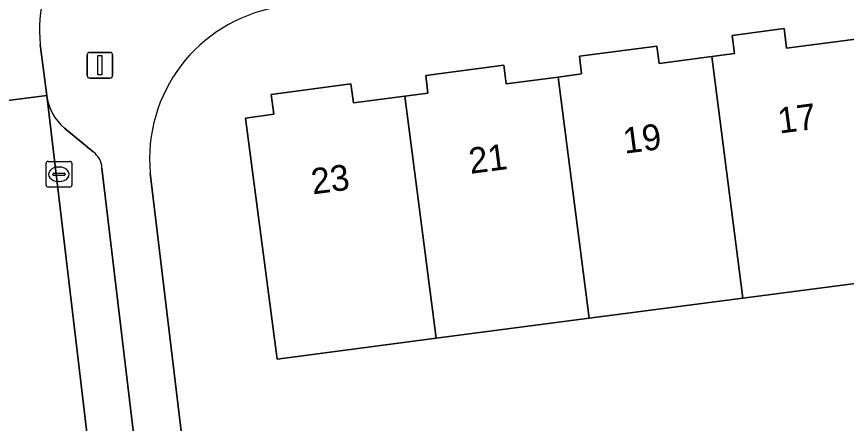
# Model space of a CAD drawing. Extents: x 162073 to 163043, y 381818 to 382561.
# Drawn here: x 162346.87 to 162379.08, y 382430.04 to 382445.83 of the extents above; entities that cross this region are included whole.
import ezdxf

# ---------------------------------------------------------------- set-up
doc = ezdxf.new("R2010")
doc.units = 0
for name, color, linetype in [('IMGEO_Erf', 7, 'Continuous'), ('IMGEO_Kolk', 7, 'Continuous'), ('IMGEO_Lichtmast', 7, 'Continuous'), ('IMGEO_Pand', 7, 'Continuous'), ('IMGEO_Pand_nummerreeks', 7, 'Continuous'), ('IMGEO_Parkeervlak_open', 7, 'Continuous'), ('IMGEO_Rijbaan_lokaal_open', 7, 'Continuous'), ('IMGEO_Voetpad_open', 7, 'Continuous')]:
    doc.layers.add(name, color=color, linetype=linetype)

msp = doc.modelspace()

# ---------------------------------------------------------------- linework, layer by layer
at = {"layer": 'IMGEO_Erf'}
for points in [[(162381.014, 382435.677), (162375.057, 382434.898), (162369.099, 382434.119), (162363.15, 382433.341), (162356.984, 382432.535), (162355.76, 382441.893), (162356.859, 382442.037), (162356.757, 382442.811), (162359.846, 382443.215), (162359.943, 382442.478), (162361.935, 382442.739), (162362.839, 382442.857), (162362.749, 382443.547), (162365.783, 382443.943), (162365.878, 382443.221), (162367.889, 382443.484), (162368.803, 382443.603), (162368.714, 382444.288), (162371.726, 382444.682), (162371.814, 382444.01), (162373.862, 382444.278), (162374.734, 382444.392), (162374.642, 382445.1), (162376.661, 382445.364), (162376.76, 382444.604), (162379.833, 382445.006)], [(162352.061, 382439.747), (162354.358, 382420.586), (162360.628, 382421.338), (162360.286, 382423.951), (162364.504, 382424.503), (162364.846, 382421.889), (162366.651, 382422.117), (162366.319, 382424.655), (162370.255, 382425.17), (162370.594, 382422.547), (162372.552, 382422.803), (162372.209, 382425.425), (162376.197, 382425.947), (162376.532, 382423.323), (162378.405, 382423.569), (162378.063, 382426.191), (162382.258, 382426.74), (162382.601, 382424.117), (162407.339, 382427.254), (162407.316, 382427.433), (162405.814, 382438.92)]]:
    msp.add_lwpolyline(points, dxfattribs=at)
msp.add_arc((162357.987, 382440.319), 5.954, 99.9538, 185.5129, dxfattribs=at)
at = {"layer": 'IMGEO_Kolk'}
for p, q in [((162348.015, 382439.284), (162348.015, 382440.136)), ((162348.09, 382440.21), (162348.942, 382440.21)), ((162348.503, 382439.99), (162348.528, 382439.99)), ((162349.016, 382440.136), (162349.016, 382439.284)), ((162348.274, 382439.704), (162348.274, 382439.716)), ((162348.712, 382439.667), (162348.314, 382439.667)), ((162348.317, 382439.753), (162348.715, 382439.753)), ((162348.758, 382439.716), (162348.758, 382439.704)), ((162348.526, 382439.43), (162348.501, 382439.43)), ((162348.942, 382439.21), (162348.09, 382439.21))]:
    msp.add_line(p, q, dxfattribs=at)
for points in [[(162348.015, 382439.284), (162348.015, 382440.136)], [(162348.09, 382440.21), (162348.942, 382440.21)], [(162349.016, 382440.136), (162349.016, 382439.284)], [(162348.942, 382439.21), (162348.09, 382439.21)]]:
    msp.add_lwpolyline(points, dxfattribs=at)
for centre, radius, start, end in [((162348.092, 382440.134), 0.0765, 91.552, 178.448), ((162348.092, 382440.134), 0.0765, 91.552, 178.448), ((162348.94, 382440.134), 0.0765, 1.552, 88.448), ((162348.94, 382440.134), 0.0765, 1.552, 88.448), ((162348.314, 382439.713), 0.0403, 85.8775, 175.7526), ((162348.311, 382439.703), 0.0366, 178.938, 274.7102), ((162348.715, 382439.71), 0.043, 264.8664, 352.4533), ((162348.719, 382439.715), 0.0386, 1.7309, 96.639), ((162348.092, 382439.286), 0.0765, 181.552, 268.448), ((162348.092, 382439.286), 0.0765, 181.552, 268.448), ((162348.94, 382439.286), 0.0765, 271.552, 358.448), ((162348.94, 382439.286), 0.0765, 271.552, 358.448)]:
    msp.add_arc(centre, radius, start, end, dxfattribs=at)
for centre, major_axis, ratio, start_param, end_param in [((162348.502, 382439.71), (-0.387, 0.002), 0.722429, 4.712389, 7.853982), ((162348.527, 382439.71), (-0.39, 0.002), 0.717154, 1.570796, 4.712389)]:
    msp.add_ellipse(centre, major_axis=major_axis, ratio=ratio, start_param=start_param, end_param=end_param, dxfattribs=at)
at = {"layer": 'IMGEO_Lichtmast'}
for p, q in [((162349.609, 382443.54), (162349.609, 382444.34)), ((162349.609, 382444.34), (162349.609, 382443.54)), ((162349.709, 382444.44), (162350.499, 382444.44)), ((162350.499, 382444.44), (162349.709, 382444.44)), ((162350.599, 382444.34), (162350.599, 382443.54)), ((162350.599, 382443.54), (162350.599, 382444.34)), ((162350.499, 382443.44), (162349.709, 382443.44)), ((162349.709, 382443.44), (162350.499, 382443.44))]:
    msp.add_line(p, q, dxfattribs=at)
msp.add_lwpolyline([(162350.029, 382444.315), (162350.179, 382444.315), (162350.179, 382443.565), (162350.029, 382443.565), (162350.029, 382444.315)], dxfattribs=at)
for centre, start, end in [((162349.709, 382444.34), 90, 180), ((162349.709, 382444.34), 90, 180), ((162350.499, 382444.34), 0, 90), ((162350.499, 382444.34), 360, 90), ((162349.709, 382443.54), 180, 270), ((162349.709, 382443.54), 180, 270), ((162350.499, 382443.54), 270, 0), ((162350.499, 382443.54), 270, 0)]:
    msp.add_arc(centre, 0.1, start, end, dxfattribs=at)
at = {"layer": 'IMGEO_Pand'}
for points in [[(162381.014, 382435.677), (162379.833, 382445.006), (162376.76, 382444.604), (162376.661, 382445.364), (162374.642, 382445.1), (162374.734, 382444.392), (162373.862, 382444.278), (162375.057, 382434.898)], [(162375.057, 382434.898), (162373.862, 382444.278), (162371.814, 382444.01), (162371.726, 382444.682), (162368.714, 382444.288), (162368.803, 382443.603), (162367.889, 382443.484), (162369.099, 382434.119)], [(162363.15, 382433.341), (162369.099, 382434.119), (162367.889, 382443.484), (162365.878, 382443.221), (162365.783, 382443.943), (162362.749, 382443.547), (162362.839, 382442.857), (162361.935, 382442.739)], [(162363.15, 382433.341), (162361.935, 382442.739), (162359.943, 382442.478), (162359.846, 382443.215), (162356.757, 382442.811), (162356.859, 382442.037), (162355.76, 382441.893), (162356.984, 382432.535)]]:
    msp.add_lwpolyline(points, close=True, dxfattribs=at)
at = {"layer": 'IMGEO_Parkeervlak_open'}
for points in [[(162348.044, 382442.765), (162351.073, 382417.25), (162359.505, 382347.328), (162359.881, 382344.208), (162361.255, 382332.813), (162367.454, 382281.495)], [(162349.842, 382440.581), (162348.727, 382441.502)], [(162353.149, 382407.065), (162354.1, 382407.187), (162352.789, 382418.064), (162350.184, 382439.951)]]:
    msp.add_lwpolyline(points, dxfattribs=at)
for centre, radius, start, end in [((162349.995, 382443.004), 1.966, 186.9815, 229.8254), ((162349.331, 382439.896), 0.855, 3.7124, 53.2789)]:
    msp.add_arc(centre, radius, start, end, dxfattribs=at)
at = {"layer": 'IMGEO_Rijbaan_lokaal_open'}
msp.add_lwpolyline([(162342.805, 382444.312), (162342.93, 382443.354), (162343.079, 382442.137), (162348.044, 382442.765), (162347.791, 382444.746)], dxfattribs=at)
msp.add_lwpolyline([(162351.073, 382417.25), (162348.044, 382442.765), (162343.079, 382442.137), (162343.442, 382439.175), (162343.465, 382438.988), (162344.493, 382430.544), (162344.514, 382430.375), (162344.521, 382430.302), (162344.575, 382429.775), (162345.223, 382424.582), (162345.763, 382419.899), (162354.563, 382346.738), (162359.505, 382347.328)], close=True, dxfattribs=at)
msp.add_arc((162352.649, 382445.321), 4.892, 94.6048, 186.7523, dxfattribs=at)
at = {"layer": 'IMGEO_Voetpad_open'}
for points in [[(162347.791, 382444.746), (162348.044, 382442.765)], [(162348.727, 382441.502), (162349.842, 382440.581)], [(162350.184, 382439.951), (162352.789, 382418.064), (162354.1, 382407.187), (162353.149, 382407.065)], [(162368.764, 382300.425), (162368.571, 382302.036), (162363.534, 382344.049), (162363.351, 382345.572), (162359.035, 382381.573), (162358.854, 382383.086), (162354.525, 382419.192), (162354.358, 382420.586), (162352.061, 382439.747)]]:
    msp.add_lwpolyline(points, dxfattribs=at)
for centre, radius, start, end in [((162352.649, 382445.321), 4.892, 94.6048, 186.7523), ((162357.987, 382440.319), 5.954, 99.9538, 185.5129), ((162349.995, 382443.004), 1.966, 186.9815, 229.8254), ((162349.331, 382439.896), 0.855, 3.7124, 53.2789)]:
    msp.add_arc(centre, radius, start, end, dxfattribs=at)

# ---------------------------------------------------------------- texts
at = {"layer": 'IMGEO_Pand_nummerreeks'}
for s, p in [('17', (162376.479, 382441.287)), ('19', (162370.472, 382440.504)), ('21', (162364.487, 382439.723)), ('23', (162358.368, 382438.925))]:
    msp.add_text(s, height=1, rotation=7.4306, dxfattribs=at).set_placement(p)

doc.saveas('drawing.dxf')
